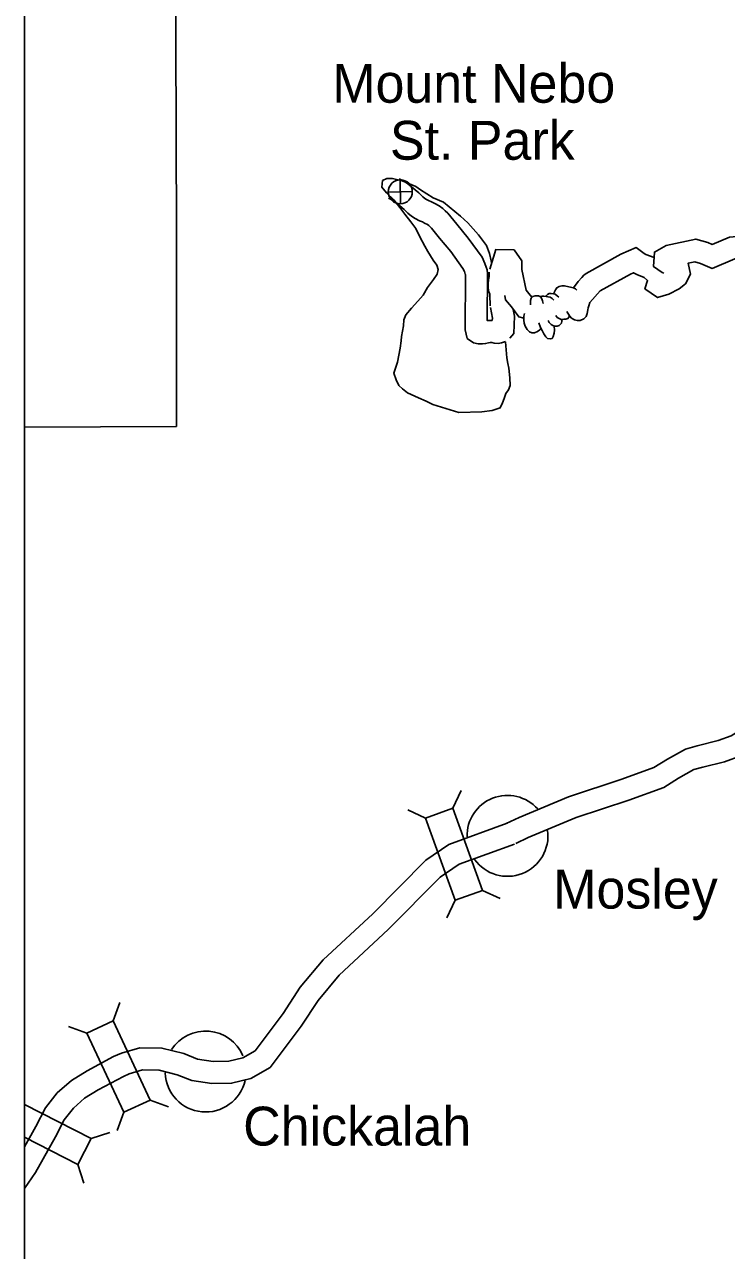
# Model space of a CAD drawing. Extents: x 1374139 to 1377472, y 1168351 to 1170484.
# Drawn here: x 1374299.2 to 1374394.6, y 1169814.6 to 1169981.2 of the extents above; entities that cross this region are included whole.
import ezdxf

# ---------------------------------------------------------------- set-up
doc = ezdxf.new("R2010")
doc.units = 0
doc.layers.add('26', color=7, linetype='Continuous')
doc.layers.add('Default', color=7, linetype='Continuous')

msp = doc.modelspace()

# ---------------------------------------------------------------- linework, layer by layer
at = {"layer": '26'}
msp.add_lwpolyline([(1374299.15, 1170388.77), (1375028.55, 1170388.77), (1375028.55, 1169604.28), (1374299.15, 1169604.28)], close=True, dxfattribs=at)
at = {"layer": 'Default'}
for p, q in [((1374350.27, 1169956.8), (1374350.2, 1169960.05)), ((1374348.61, 1169958.39), (1374351.86, 1169958.46)), ((1374357.36, 1169874.68), (1374358.49, 1169877.07)), ((1374353.64, 1169873.33), (1374351.25, 1169874.45)), ((1374357.68, 1169862.16), (1374356.56, 1169859.77)), ((1374361.4, 1169863.5), (1374363.79, 1169862.38)), ((1374311.22, 1169845.79), (1374312.13, 1169848.27)), ((1374307.63, 1169844.12), (1374305.15, 1169845.03)), ((1374299.15, 1169834.41), (1374299.15, 1169829.96)), ((1374308.21, 1169829.78), (1374299.15, 1169834.41)), ((1374316.23, 1169835.02), (1374318.71, 1169834.11)), ((1374312.64, 1169833.35), (1374311.74, 1169830.87)), ((1374308.21, 1169829.78), (1374310.73, 1169830.59)), ((1374299.15, 1169829.96), (1374306.41, 1169826.25)), ((1374306.41, 1169826.25), (1374308.21, 1169829.78)), ((1374306.41, 1169826.25), (1374307.23, 1169823.74))]:
    msp.add_line(p, q, dxfattribs=at)
for points in [[(1374299.15, 1169926.43), (1374319.81, 1169926.55), (1374319.79, 1169952.79), (1374319.74, 1169979.38), (1374319.7, 1169994.9)], [(1374364.14, 1169929.76), (1374363.82, 1169929.07), (1374362.73, 1169928.71), (1374361.3, 1169928.55), (1374358.17, 1169928.45), (1374354.64, 1169929.52), (1374353.74, 1169929.97), (1374352.71, 1169930.43), (1374351.22, 1169931.13), (1374350.54, 1169931.65), (1374350.03, 1169932.12), (1374349.65, 1169932.87), (1374349.35, 1169933.8), (1374349.69, 1169934.73), (1374349.83, 1169935.28), (1374350.23, 1169937.16), (1374350.37, 1169938.17), (1374350.41, 1169938.76), (1374350.68, 1169940.2), (1374350.73, 1169941.03), (1374350.98, 1169941.71), (1374351.77, 1169942.62), (1374352.6, 1169943.59), (1374353.34, 1169944.37), (1374353.94, 1169945.42), (1374354.72, 1169946.5), (1374355.23, 1169947.26), (1374355.37, 1169947.85), (1374355.18, 1169948.48), (1374354.71, 1169949.16), (1374353.99, 1169950.32), (1374353.56, 1169951.04), (1374352.9, 1169952.31), (1374352.32, 1169953.46), (1374351.65, 1169954.33), (1374350.85, 1169955.38), (1374350.15, 1169956.3), (1374349.33, 1169957.33), (1374348.35, 1169958.28), (1374347.7, 1169959.08), (1374347.83, 1169959.96), (1374348.39, 1169960.23), (1374349.15, 1169960.25), (1374350.48, 1169959.94), (1374352.33, 1169959.14), (1374352.97, 1169958.7), (1374354.68, 1169957.59), (1374356.09, 1169957.01), (1374358.4, 1169955.13), (1374359.4, 1169954.2), (1374360.85, 1169952.57), (1374361.93, 1169951.13), (1374362.37, 1169950.03), (1374362.6, 1169949.06), (1374362.62, 1169948.82)], [(1374362.72, 1169940.93), (1374362.5, 1169940.94), (1374362.07, 1169940.93), (1374362.05, 1169940.92), (1374362.08, 1169947.35), (1374362.04, 1169947.83), (1374361.9, 1169948.21), (1374361.74, 1169948.7), (1374361.34, 1169949.54), (1374359.47, 1169952.14), (1374357.9, 1169954.04), (1374356.69, 1169955.52), (1374356.34, 1169955.85), (1374356, 1169956.17), (1374355.53, 1169956.51), (1374354.93, 1169956.84), (1374354.46, 1169957.08), (1374354.05, 1169957.24), (1374353.77, 1169957.38), (1374353.57, 1169957.51), (1374353.3, 1169957.74), (1374352.76, 1169958.27), (1374351.5, 1169959.31), (1374351.08, 1169959.66), (1374350.51, 1169959.96), (1374350.08, 1169960.2)], [(1374364.52, 1169938.1), (1374364.27, 1169938), (1374364, 1169937.92), (1374363.52, 1169937.83), (1374363, 1169937.87), (1374362.69, 1169937.93), (1374362.48, 1169937.94), (1374362.43, 1169937.94), (1374362.2, 1169937.89), (1374361.83, 1169937.81), (1374361.38, 1169937.76), (1374360.82, 1169937.78), (1374360.19, 1169937.92), (1374359.31, 1169938.51), (1374359.04, 1169939.69), (1374359.08, 1169947.18), (1374359.06, 1169947.23), (1374358.95, 1169947.58), (1374358.75, 1169948), (1374357.09, 1169950.31), (1374355.58, 1169952.14), (1374354.48, 1169953.48), (1374354.28, 1169953.67), (1374354.09, 1169953.85), (1374353.92, 1169953.97), (1374353.53, 1169954.19), (1374353.25, 1169954.33), (1374352.82, 1169954.49), (1374352.24, 1169954.79), (1374351.76, 1169955.12), (1374351.27, 1169955.53), (1374350.75, 1169956.04), (1374349.58, 1169957), (1374349.4, 1169957.16), (1374349.09, 1169957.32), (1374348.64, 1169957.56)], [(1374403.99, 1169952.96), (1374399.79, 1169952.7), (1374394.97, 1169952.25), (1374392.64, 1169951.28), (1374392.04, 1169951.53), (1374390.38, 1169952), (1374386.36, 1169951.15), (1374384.78, 1169950.23), (1374384.65, 1169948.27), (1374385.83, 1169947.45), (1374386.05, 1169947.37)], [(1374368.12, 1169944.09), (1374368.1, 1169944.1), (1374367.69, 1169944.63), (1374367.33, 1169945.08), (1374366.74, 1169947.86), (1374366.75, 1169949.05), (1374365.7, 1169950.56), (1374363.2, 1169950.57), (1374362.39, 1169947.93)], [(1374384.72, 1169949.5), (1374383.61, 1169949.92), (1374383.36, 1169950.05), (1374382.27, 1169950.84), (1374380.21, 1169949.94), (1374375.5, 1169947.35)], [(1374404.18, 1169949.97), (1374400.03, 1169949.71), (1374395.7, 1169949.3), (1374392.64, 1169948.03), (1374391.05, 1169948.69), (1374390.28, 1169948.91), (1374389.34, 1169948.72), (1374389.69, 1169947.22), (1374388.98, 1169945.91), (1374388.12, 1169945.24), (1374386.73, 1169944.54), (1374385.2, 1169944.06), (1374383.48, 1169945.25), (1374383.85, 1169946.37), (1374383.38, 1169946.8), (1374382.37, 1169947.18), (1374381.92, 1169947.42), (1374381.53, 1169947.25), (1374377.4, 1169944.97)], [(1374362.32, 1169947.53), (1374362.3, 1169946.91), (1374362.2, 1169946.48), (1374362.17, 1169945.96), (1374362.17, 1169945.4), (1374362.28, 1169944.84), (1374362.38, 1169944.58), (1374362.42, 1169944.43), (1374362.46, 1169942.93)], [(1374375.5, 1169947.35), (1374375.19, 1169947.09), (1374374.9, 1169946.8), (1374374.4, 1169946.26), (1374373.77, 1169945.39)], [(1374374.23, 1169945.07), (1374374.05, 1169945.25), (1374373.77, 1169945.39), (1374373.13, 1169945.52), (1374372.56, 1169945.64), (1374372.19, 1169945.65), (1374371.81, 1169945.57), (1374371.49, 1169945.39), (1374371.31, 1169945.09), (1374371.13, 1169944.75), (1374371.08, 1169944.56)], [(1374367.01, 1169941.28), (1374366.34, 1169941.46), (1374365.33, 1169942.78), (1374364.55, 1169943.75), (1374364.43, 1169944.33)], [(1374369.21, 1169944.19), (1374369.02, 1169944.29), (1374368.77, 1169944.31), (1374368.54, 1169944.3), (1374368.26, 1169944.22), (1374368.04, 1169943.96), (1374367.94, 1169943.64), (1374367.93, 1169943.46), (1374367.93, 1169943.05)], [(1374369.21, 1169944.19), (1374369.32, 1169944.1), (1374369.46, 1169943.89), (1374369.57, 1169943.62), (1374369.66, 1169943.26)], [(1374371.11, 1169943.71), (1374370.85, 1169943.92), (1374370.58, 1169944.09), (1374370.3, 1169944.17), (1374370.06, 1169944.22), (1374369.76, 1169944.24), (1374369.47, 1169944.24), (1374369.26, 1169944.19)], [(1374371.8, 1169944.1), (1374371.56, 1169944.3), (1374371.27, 1169944.52), (1374371.07, 1169944.57), (1374370.73, 1169944.62), (1374370.45, 1169944.59), (1374370.23, 1169944.48), (1374370.07, 1169944.3), (1374370.03, 1169944.21)], [(1374377.41, 1169944.97), (1374376.01, 1169943.39)], [(1374362.48, 1169942.69), (1374362.74, 1169941.28), (1374362.73, 1169940.94)], [(1374365.58, 1169942.43), (1374365.75, 1169941.51), (1374365.67, 1169939.17), (1374365.12, 1169938.52)], [(1374369.35, 1169939.85), (1374369.18, 1169939.66), (1374368.86, 1169939.43), (1374368.48, 1169939.28), (1374368.1, 1169939.28), (1374367.79, 1169939.42), (1374367.47, 1169939.74), (1374367.22, 1169940.16), (1374367.05, 1169940.6), (1374367, 1169941), (1374367.04, 1169941.55), (1374367.13, 1169941.89)], [(1374376.01, 1169943.39), (1374375.87, 1169942.95), (1374375.77, 1169942.67), (1374375.72, 1169942.4), (1374375.64, 1169941.88), (1374375.5, 1169941.48), (1374375.19, 1169941.17), (1374374.67, 1169940.95), (1374374.29, 1169940.92), (1374373.9, 1169941.02), (1374373.51, 1169941.28), (1374373.24, 1169941.56), (1374372.88, 1169942.17)], [(1374371.15, 1169940.16), (1374371.17, 1169939.62), (1374371.13, 1169939.22), (1374371.02, 1169938.76), (1374370.85, 1169938.5), (1374370.62, 1169938.44), (1374370.26, 1169938.5), (1374370, 1169938.74), (1374369.73, 1169939.13), (1374369.49, 1169939.57), (1374369.29, 1169939.98), (1374369.05, 1169940.61)], [(1374372.22, 1169941.09), (1374372.19, 1169940.83), (1374372.12, 1169940.6), (1374371.97, 1169940.41), (1374371.81, 1169940.28), (1374371.53, 1169940.17), (1374371.25, 1169940.17), (1374370.98, 1169940.25), (1374370.75, 1169940.38), (1374370.48, 1169940.67), (1374370.35, 1169940.96)], [(1374373.23, 1169941.58), (1374373.15, 1169941.4), (1374373.01, 1169941.22), (1374372.72, 1169941.11), (1374372.48, 1169941.11), (1374372.1, 1169941.1), (1374371.9, 1169941.17), (1374371.55, 1169941.37), (1374371.38, 1169941.64)], [(1374364.53, 1169938.04), (1374364.69, 1169935.85), (1374364.86, 1169935.12), (1374364.98, 1169934.45), (1374365.12, 1169933.16), (1374365.15, 1169932.13), (1374364.92, 1169931.52), (1374364.56, 1169931.02), (1374364.33, 1169930.35), (1374364.14, 1169929.76)], [(1374420.77, 1169904.22), (1374413.59, 1169899.32), (1374406.47, 1169894.65), (1374404.47, 1169893.12), (1374402.56, 1169891.23), (1374401, 1169889.31), (1374399.35, 1169887.2), (1374397.62, 1169885.98), (1374395.22, 1169884.5), (1374393.43, 1169883.86), (1374390.59, 1169883.16), (1374388.99, 1169882.7), (1374386.54, 1169881.35), (1374384.71, 1169880.2), (1374380.32, 1169878.6), (1374373.1, 1169876.22), (1374366.39, 1169873.43), (1374364.61, 1169872.57)], [(1374422.8, 1169901.97), (1374415.26, 1169896.83), (1374408.21, 1169892.2), (1374406.44, 1169890.85), (1374404.79, 1169889.21), (1374403.35, 1169887.44), (1374401.44, 1169885.01), (1374399.27, 1169883.47), (1374396.53, 1169881.79), (1374394.3, 1169880.99), (1374391.36, 1169880.26), (1374390.14, 1169879.91), (1374388.06, 1169878.76), (1374386.04, 1169877.49), (1374381.3, 1169875.77), (1374374.15, 1169873.4), (1374367.62, 1169870.69), (1374365.92, 1169869.87)], [(1374364.76, 1169872.63), (1374356.83, 1169869.76), (1374353.71, 1169867.59), (1374346.51, 1169860.33), (1374339.73, 1169854.05), (1374336.63, 1169850.33), (1374334.31, 1169846.77), (1374330.51, 1169841.72), (1374328.81, 1169840.76), (1374326.91, 1169840.29), (1374324.81, 1169840.25), (1374322.68, 1169840.59), (1374320.82, 1169841.32), (1374317.82, 1169842.07), (1374314.81, 1169842.11), (1374312.32, 1169841.4), (1374311.26, 1169840.91), (1374307.69, 1169838.98), (1374305.54, 1169837.69), (1374303.61, 1169835.99), (1374301.99, 1169833.95), (1374300.7, 1169831.43), (1374299.15, 1169828.64)], [(1374365.77, 1169869.8), (1374358.22, 1169867.07), (1374355.64, 1169865.28), (1374348.6, 1169858.18), (1374341.91, 1169851.98), (1374339.05, 1169848.54), (1374336.76, 1169845.04), (1374332.53, 1169839.42), (1374329.93, 1169837.95), (1374327.3, 1169837.3), (1374324.6, 1169837.24), (1374321.88, 1169837.68), (1374319.9, 1169838.46), (1374317.44, 1169839.08), (1374315.21, 1169839.11), (1374313.37, 1169838.58), (1374312.61, 1169838.23), (1374309.18, 1169836.38), (1374307.32, 1169835.26), (1374305.8, 1169833.91), (1374304.53, 1169832.32), (1374303.35, 1169830.01), (1374300.64, 1169825.15), (1374299.15, 1169822.99)]]:
    msp.add_lwpolyline(points, dxfattribs=at)
for points in [[(1374361.4, 1169863.5), (1374357.36, 1169874.68), (1374353.64, 1169873.33), (1374357.68, 1169862.16)], [(1374316.23, 1169835.02), (1374311.22, 1169845.79), (1374307.63, 1169844.12), (1374312.64, 1169833.35)]]:
    msp.add_lwpolyline(points, close=True, dxfattribs=at)
msp.add_circle((1374350.23, 1169958.43), 1.63, dxfattribs=at)
for centre, start, end in [((1374364.8, 1169870.91), 41.689, 181.3804), ((1374364.8, 1169870.91), 215.6185, 7.6404), ((1374323.77, 1169838.89), 22.9321, 147.0948), ((1374323.77, 1169838.89), 182.07, 347.1063)]:
    msp.add_arc(centre, 5.5, start, end, dxfattribs=at)

# ---------------------------------------------------------------- texts
for s, p in [('Mount Nebo', (1374340.98, 1169970.53)), ('St. Park', (1374348.82, 1169962.79)), ('Mosley', (1374371.01, 1169861.03)), ('Chickalah', (1374328.87, 1169828.83))]:
    msp.add_text(s, height=5.28, dxfattribs=at).set_placement(p)

doc.saveas('drawing.dxf')
